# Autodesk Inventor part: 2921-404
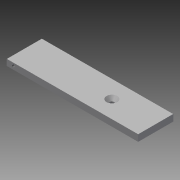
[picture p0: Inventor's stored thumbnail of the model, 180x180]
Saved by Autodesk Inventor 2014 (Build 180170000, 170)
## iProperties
Company: NHTSA/VRTC
Created: 2012-12
Part Number: 2921-404
Material: Steel, Mild
Document SubType Name: Modeling
Designer: Mike Vanvoorhis
Density: 7.86 g/cm^3
Mass: 5708.24 g
Surface Area: 982.766 cm^2
Volume: 726.239 cm^3
Project: CHILD SIDE IMPACT SLED
Description: ANTI-REBOUND FIXTURE STOP PLATE
Stock Number: PL 19.1 (3/4") x 101.6 (4") x 381.0 (15")
Appearance: Steel
DESIGN DATE: 2012-11-05
Author: Dave Walker
Title: Anti-Rebound Fixture Stop Pate
Subject: Child Side Impact Sled
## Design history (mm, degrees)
sketch "Sketch1"
  geometry: L1 (0, 0)-(381, 0); L2 (381, 0)-(381, 19.05); L3 (381, 19.05)-(0, 19.05); L4 (0, 19.05)-(0, 0); C1 r 3.61 at (19.05, 9.525)
  constraints: 8 end point, 2 parallel, 1 centre point, 1 horizontal, 1 perpendicular
  dimensions: "d0" = 381 distance of L3.end L2.end; "d10" = 19.05 distance from line of L4 C1.centre
extrude "Extrusion1" new body sketch "Sketch1" distance "d2" = 50.8; taper "d3" = 0 deg; dims "d8" = 50.8, "d9" = 0
sketch "Sketch3"
  geometry: L1 (0, 0)-(0, 19.05) reference; C1 r 4.762 at (19.05, 9.525)
  constraints: 1 centre point
  dimensions: "d11" = 9.525 diameter of C1; "d12" = 19.05 distance from line of L1 C1.centre
hole "Hole1" sketch "Sketch3" at (19.05, 9.525) diameter "d13" = 7.7978; stored, may be unused: countersink angle "d17" = 82 deg, drill point angle "d19" = 118 deg; dims "d14" = 19.05, "d15" = 9.525, "d16" = 6.35, "d18" = 25.4
sketch "Sketch5"
  geometry: L1 (0, 19.05)-(0, 0) reference; C1 r 4.763 at (-19.05, 9.525)
  constraints: 1 centre point
  dimensions: "d20" = 9.525 diameter of C1; "d21" = 19.05 distance from line of L1 C1.centre
hole "Hole2" sketch "Sketch5" at (-19.05, 9.525) diameter "d22" = 7.7978; stored, may be unused: countersink angle "d26" = 82 deg, drill point angle "d28" = 118 deg; dims "d23" = 19.05, "d24" = 9.525, "d25" = 6.35, "d27" = 25.4
sketch "Sketch6"
  geometry: L1 (381, 0)-(0, 0) reference; L2 (381, 0)-(381, -101.6) reference; C1 r 6.35 at (254, -50.8); 1 further point
  constraints: 1 centre point
  dimensions: "d29" = 12.7 diameter of C1; "d30" = 50.8 distance from line of L1 C1.centre; "d31" = 127 distance from line of L2 C1.centre
hole "Hole3" sketch "Sketch6" at (254, -50.8) diameter "d32" = 12.7; stored, may be unused: countersink angle "d36" = 82 deg, drill point angle "d38" = 118 deg; dims "d33" = 11.7602, "d34" = 31.75, "d35" = 6.35, "d37" = 25.4
sketch "Sketch7"
  geometry: L1 (0, 0)-(381, 0) reference; L2 (381, 101.6)-(0, 101.6) reference; L3 (311.15, 101.6)-(311.15, 0); L4 (311.15, 50.8)-(311.15, 69.85); L5 (311.15, 69.85)-(311.15, 88.9); L6 (311.15, 50.8)-(311.15, 31.75); L7 (311.15, 31.75)-(311.15, 12.7); C1 r 7.938 at (311.15, 50.8); C2 r 7.937 at (311.15, 12.7); C3 r 7.938 at (311.15, 31.75); C4 r 7.937 at (311.15, 69.85); C5 r 7.937 at (311.15, 88.9); 1 further point
  constraints: 10 end point, 6 point on line, 5 centre point, 4 coincident, 1 midpoint, 1 perpendicular
  dimensions: "d39" = 69.85 distance of L3.start L2.start; "d40" = 15.875 diameter of C1; "d41" = 19.05 distance of L4.start L4.end; "d42" = 19.05 distance of L4.end L5.end; "d43" = 19.05 distance of L4.start L6.end; "d44" = 19.05 distance of L6.end L7.end; "d45" = 15.875 diameter of C2; "d46" = 15.875 diameter of C3; "d47" = 15.875 diameter of C4; "d48" = 15.875 diameter of C5
hole "Hole4" sketch "Sketch7" at (311.15, 12.7), (311.15, 31.75), (311.15, 50.8), (311.15, 69.85), (311.15, 88.9) diameter "d49" = 15.875; stored, may be unused: countersink angle "d53" = 82 deg, drill point angle "d55" = 0 deg; dims "d50" = 19.05, "d51" = 9.525, "d52" = 6.35, "d54" = 3.175
sketch "Sketch8"
  geometry: L1 (0, 0)-(0, 19.05) reference; L2 (0, 19.05)-(381, 19.05) reference; L3 (0, 0)-(0, 17.78); L4 (0, 17.78)-(381, 19.05); L5 (0, 17.78)-(0, 19.05); L6 (0, 19.05)-(381, 19.05)
  constraints: 8 end point, 1 collinear, 1 point on line
  dimensions: "d57" = 17.78 distance of L1.start L3.end
extrude "Extrusion2" cut sketch "Sketch8" distance "d58" = 101.6; taper "d59" = 0 deg
body "Solid1"
